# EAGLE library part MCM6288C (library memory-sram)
MEMORY
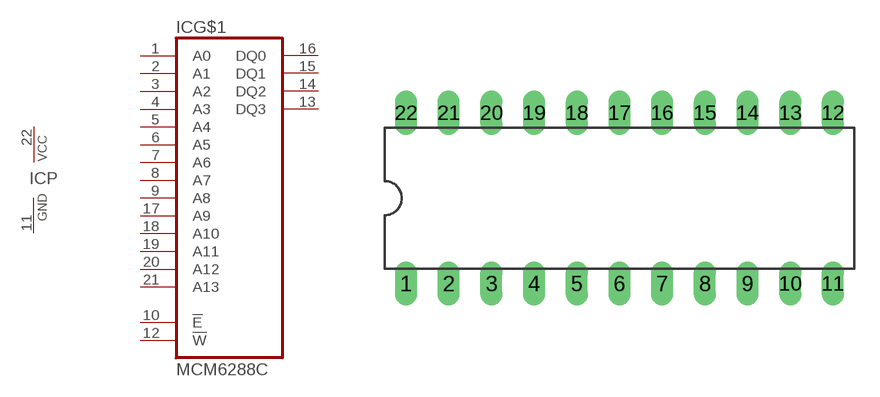
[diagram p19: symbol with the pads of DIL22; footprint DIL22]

Designator prefix IC; gates G$1=CM6288C P=PWRN

## MCM6288C  [DIL22]
1  G$1:A0  in
2  G$1:A1  in
3  G$1:A2  in
4  G$1:A3  in
5  G$1:A4  in
6  G$1:A5  in
7  G$1:A6  in
8  G$1:A7  in
9  G$1:A8  in
10  G$1:!E  in
11  P:GND  pwr
12  G$1:!W  in
13  G$1:DQ3
14  G$1:DQ2
15  G$1:DQ1
16  G$1:DQ0
17  G$1:A9  in
18  G$1:A10  in
19  G$1:A11  in
20  G$1:A12  in
21  G$1:A13  in
22  P:VCC  pwr

## Footprint DIL22 (pad centres in mm)
Dual In Line Package
drill 0.813 long: 1 -12.7,-5.08; 2 -10.16,-5.08; 3 -7.62,-5.08; 4 -5.08,-5.08; 5 -2.54,-5.08; 6 0,-5.08; 7 2.54,-5.08; 8 5.08,-5.08; 9 7.62,-5.08; 10 10.16,-5.08; 11 12.7,-5.08; 12 12.7,5.08; 13 10.16,5.08; 14 7.62,5.08; 15 5.08,5.08; 16 2.54,5.08; 17 0,5.08; 18 -2.54,5.08; 19 -5.08,5.08; 20 -7.62,5.08; 21 -10.16,5.08; 22 -12.7,5.08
